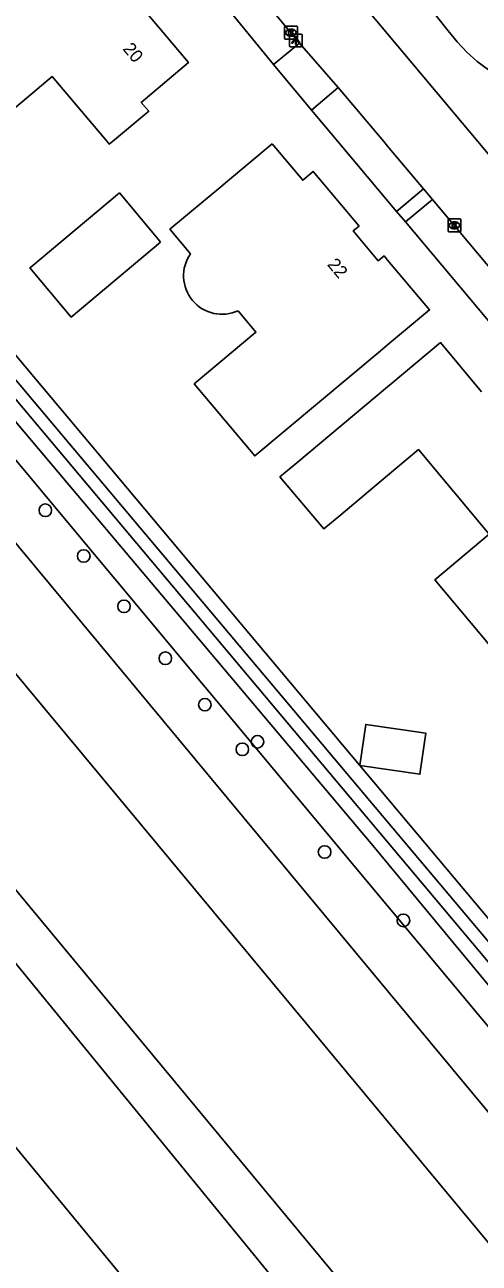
# Model space of a CAD drawing. Extents: x 157321 to 158827, y 386650 to 388532.
# Drawn here: x 157971.7 to 158007.1, y 386912.6 to 387009.1 of the extents above; entities that cross this region are included whole.
import ezdxf

# ---------------------------------------------------------------- set-up
doc = ezdxf.new("R2010")
doc.units = 0
for name, color, linetype in [('IMGEO_Boom', 7, 'Continuous'), ('IMGEO_Fietspad_gesloten', 7, 'Continuous'), ('IMGEO_Groenvoorziening', 7, 'Continuous'), ('IMGEO_Kolk', 7, 'Continuous'), ('IMGEO_Lichtpunt', 7, 'Continuous'), ('IMGEO_Loofbos', 7, 'Continuous'), ('IMGEO_Pand', 7, 'Continuous'), ('IMGEO_Pand_nummerreeks', 7, 'Continuous'), ('IMGEO_Rijbaan_lokaal_gesloten', 7, 'Continuous'), ('IMGEO_Voetpad_open', 7, 'Continuous'), ('IMGEO_Waterloop', 7, 'Continuous')]:
    doc.layers.add(name, color=color, linetype=linetype)

msp = doc.modelspace()

# ---------------------------------------------------------------- linework, layer by layer
at = {"layer": 'IMGEO_Boom'}
for centre in [(157973.337, 386971.279), (157976.332, 386967.714), (157979.465, 386963.801), (157982.691, 386959.755), (157985.765, 386956.139), (157989.865, 386953.249), (157988.683, 386952.66), (157995.089, 386944.665), (158001.231, 386939.336)]:
    msp.add_circle(centre, 0.489, dxfattribs=at)
at = {"layer": 'IMGEO_Fietspad_gesloten'}
msp.add_lwpolyline([(158000, 387014.593), (158004.726, 387008.62), (158005.406, 387007.76), (158006.16, 387006.964), (158006.983, 387006.238), (158007.867, 387005.589), (158008.805, 387005.021), (158009.791, 387004.54), (158010.815, 387004.148), (158011.87, 387003.85), (158012.948, 387003.647), (158014.039, 387003.541), (158015.136, 387003.533), (158016.229, 387003.623), (158017.31, 387003.81), (158018.369, 387004.093), (158019.399, 387004.47), (158020.111, 387004.794), (158022.082, 387005.73), (158023.75, 387006.523)], dxfattribs=at)
at = {"layer": 'IMGEO_Groenvoorziening'}
for points in [[(158032.15, 386861.115), (158029.801, 386864.464), (158027.255, 386867.666), (158023.027, 386872.512), (158000, 386900.579), (157928.219, 386988.333), (157917.785, 387000), (157871.791, 387051.43), (157870.977, 387052.41)], [(157915.669, 387039.524), (157916.246, 387034.499), (157917.326, 387029.652), (157918.224, 387026.707), (157925.534, 387014.398), (157933.739, 387003.394), (158036.298, 386879.994), (158040.875, 386875.274), (158045.999, 386870.991), (158051.541, 386867.268), (158057.356, 386864.191), (158059.718, 386863.157), (158065.313, 386860.377), (158069.288, 386859.404), (158071.922, 386859.047), (158074.577, 386858.967), (158077.228, 386859.164), (158080.09, 386859.682), (158109.645, 386869.131), (158107.666, 386875.322)], [(157937.472, 387021.971), (157943.823, 387013.736), (157955.389, 387000), (158000, 386947.022), (158042.278, 386896.814)], [(157991.12, 387006.005), (157981.864, 387017.312), (157978.709, 387020.934)], [(157938.087, 387014.677), (157950.334, 387000), (158000, 386940.482), (158039.093, 386893.634)], [(157939.879, 387006.192), (157945.025, 387000), (158000, 386933.844), (158041.131, 386884.348)], [(157951.635, 387006.472), (157997.832, 386951.408)], [(158000.702, 386994.555), (157996.119, 387000), (157994.061, 387002.445)], [(157923.674, 387000), (157926.719, 386995.12), (158000, 386906.805), (158021.479, 386880.919), (158025.173, 386876.788)], [(158018.379, 386973.505), (158001.394, 386993.731)], [(157997.832, 386951.408), (158016.34, 386929.351), (158048.856, 386891.347), (158052.006, 386888.362), (158054.735, 386886.23), (158061.143, 386882.788), (158063.836, 386881.61), (158066.74, 386880.636), (158072.605, 386879.295), (158075.571, 386878.874), (158081.422, 386878.627), (158087.103, 386878.964), (158090.042, 386879.509), (158092.91, 386880.238), (158101.35, 386883.538), (158104.009, 386884.795), (158111.36, 386888.673), (158097.876, 386904.822), (158091.265, 386912.857)]]:
    msp.add_lwpolyline(points, dxfattribs=at)
at = {"layer": 'IMGEO_Kolk'}
for p, q in [((157991.969, 387008.048), (157991.969, 387008.9)), ((157992.044, 387008.974), (157992.896, 387008.974)), ((157992.457, 387008.754), (157992.482, 387008.754)), ((157992.97, 387008.9), (157992.97, 387008.048)), ((157992.896, 387007.974), (157992.044, 387007.974)), ((157992.48, 387008.194), (157992.455, 387008.194)), ((158004.706, 386993.048), (158004.706, 386993.9)), ((158004.781, 386993.974), (158005.633, 386993.974)), ((158005.217, 386993.194), (158005.192, 386993.194)), ((158005.194, 386993.754), (158005.219, 386993.754)), ((158005.707, 386993.9), (158005.707, 386993.048)), ((158005.633, 386992.974), (158004.781, 386992.974))]:
    msp.add_line(p, q, dxfattribs=at)
for points in [[(157991.969, 387008.048), (157991.969, 387008.9)], [(157992.044, 387008.974), (157992.896, 387008.974)], [(157992.29, 387008.674), (157992.413, 387008.674), (157992.413, 387008.523), (157992.543, 387008.674), (157992.707, 387008.674), (157992.561, 387008.523), (157992.714, 387008.274), (157992.562, 387008.274), (157992.477, 387008.438), (157992.413, 387008.371), (157992.413, 387008.274), (157992.29, 387008.274), (157992.29, 387008.674)], [(157992.97, 387008.9), (157992.97, 387008.048)], [(157992.896, 387007.974), (157992.044, 387007.974)], [(158004.706, 386993.048), (158004.706, 386993.9)], [(158004.781, 386993.974), (158005.633, 386993.974)], [(158005.027, 386993.674), (158005.15, 386993.674), (158005.15, 386993.523), (158005.28, 386993.674), (158005.444, 386993.674), (158005.298, 386993.523), (158005.451, 386993.274), (158005.299, 386993.274), (158005.214, 386993.438), (158005.15, 386993.371), (158005.15, 386993.274), (158005.027, 386993.274), (158005.027, 386993.674)], [(158005.707, 386993.9), (158005.707, 386993.048)], [(158005.633, 386992.974), (158004.781, 386992.974)]]:
    msp.add_lwpolyline(points, dxfattribs=at)
for centre, start, end in [((157992.046, 387008.898), 91.55205, 178.44795), ((157992.046, 387008.898), 91.55205, 178.44795), ((157992.894, 387008.898), 1.55205, 88.44795), ((157992.894, 387008.898), 1.55205, 88.44795), ((157992.046, 387008.05), 181.55205, 268.44795), ((157992.046, 387008.05), 181.55205, 268.44795), ((157992.894, 387008.05), 271.55205, 358.44795), ((157992.894, 387008.05), 271.55205, 358.44795), ((158004.783, 386993.898), 91.55205, 178.44795), ((158004.783, 386993.898), 91.55205, 178.44795), ((158005.631, 386993.898), 1.55205, 88.44795), ((158005.631, 386993.898), 1.55205, 88.44795), ((158004.783, 386993.05), 181.55205, 268.44795), ((158004.783, 386993.05), 181.55205, 268.44795), ((158005.631, 386993.05), 271.55205, 358.44795), ((158005.631, 386993.05), 271.55205, 358.44795)]:
    msp.add_arc(centre, 0.0765, start, end, dxfattribs=at)
for centre, major_axis, ratio, start_param, end_param in [((157992.456, 387008.474), (-0.387, 0.002), 0.722429, 4.712389, 7.853982), ((157992.481, 387008.474), (-0.39, 0.002), 0.717154, 1.570796, 4.712389), ((158005.193, 386993.474), (-0.387, 0.002), 0.722429, 4.712389, 7.853982), ((158005.218, 386993.474), (-0.39, 0.002), 0.717154, 1.570796, 4.712389)]:
    msp.add_ellipse(centre, major_axis=major_axis, ratio=ratio, start_param=start_param, end_param=end_param, dxfattribs=at)
at = {"layer": 'IMGEO_Lichtpunt'}
for p, q in [((157992.35, 387008.271), (157992.35, 387007.464)), ((157992.35, 387008.271), (157992.35, 387007.464)), ((157993.252, 387008.366), (157992.444, 387008.366)), ((157993.252, 387008.366), (157992.444, 387008.366)), ((157993.346, 387007.464), (157993.346, 387008.271)), ((157993.346, 387007.464), (157993.346, 387008.271)), ((157992.444, 387007.37), (157993.252, 387007.37)), ((157992.444, 387007.37), (157993.252, 387007.37))]:
    msp.add_line(p, q, dxfattribs=at)
for points in [[(157992.724, 387007.935), (157992.763, 387007.907), (157992.575, 387007.645), (157992.537, 387007.672), (157992.724, 387007.935)], [(157992.826, 387007.887), (157992.873, 387007.887), (157992.873, 387007.565), (157992.826, 387007.565), (157992.826, 387007.887)], [(157992.936, 387007.907), (157992.974, 387007.934), (157993.161, 387007.672), (157993.122, 387007.644), (157992.936, 387007.907)]]:
    msp.add_lwpolyline(points, dxfattribs=at)
msp.add_circle((157992.849, 387008.069), 0.0994, dxfattribs=at)
for centre, start, end in [((157992.444, 387008.271), 90, 180), ((157992.444, 387008.271), 90, 180), ((157993.252, 387008.271), 0, 90), ((157993.252, 387008.271), 0, 90), ((157992.444, 387007.464), 180, 270), ((157992.444, 387007.464), 180, 270), ((157993.252, 387007.464), 270, 0), ((157993.252, 387007.464), 270, 360)]:
    msp.add_arc(centre, 0.0946, start, end, dxfattribs=at)
at = {"layer": 'IMGEO_Loofbos'}
msp.add_lwpolyline([(158038.982, 386833.681), (158041.689, 386835.911), (158004.244, 386881.346), (157903.574, 387003.498), (157866.09, 387048.992)], dxfattribs=at)
at = {"layer": 'IMGEO_Pand'}
for points in [[(157980.253, 387011.189), (157984.479, 387006.146), (157980.809, 387003.048), (157981.39, 387002.359), (157978.567, 387000), (157978.32, 386999.794), (157978.146, 387000), (157973.873, 387005.054), (157967.839, 387000), (157966.986, 386999.286), (157966.386, 387000), (157961.965, 387005.291), (157969.332, 387011.446), (157965.549, 387015.974), (157970.468, 387020.084), (157973.65, 387016.275), (157976.795, 387012.511), (157978.867, 387010.031), (157980.253, 387011.189)], [(157984.645, 386991.256), (157983.045, 386993.162), (157987.163, 386996.612), (157987.378, 386996.792), (157990.995, 386999.823)], [(157990.995, 386999.823), (157993.395, 386996.984), (157994.208, 386997.671), (157997.781, 386993.415), (157997.322, 386993.03), (157999.27, 386990.709), (157999.729, 386991.094), (158000, 386990.771), (158003.264, 386986.881), (158000, 386984.153), (157999.428, 386983.675), (157989.657, 386975.511), (157984.94, 386981.114), (157989.74, 386985.139), (157988.369, 386986.825)], [(157982.31, 386992.161), (157982.121, 386992.386), (157979.117, 386995.999), (157972.203, 386990.223), (157972.139, 386990.169), (157975.353, 386986.322), (157982.31, 386992.161)], [(158000, 386980.903), (158000.279, 386981.136), (158004.114, 386984.343), (158007.316, 386980.509)], [(158009.198, 386959.269), (158003.685, 386965.861), (158007.917, 386969.425), (158002.409, 386976), (158000, 386973.982), (157996.362, 386970.934), (157995.044, 386969.83), (157991.606, 386973.883), (157992.925, 386974.986), (158000, 386980.903)], [(157997.832, 386951.408), (157998.299, 386954.602), (158002.985, 386953.918), (158002.518, 386950.723), (157997.832, 386951.408)]]:
    msp.add_lwpolyline(points, dxfattribs=at)
msp.add_arc((157987.106, 386989.544), 2.998, 145.17411, 294.91612, dxfattribs=at)
at = {"layer": 'IMGEO_Rijbaan_lokaal_gesloten'}
for points in [[(157972.38, 387041.273), (158000, 387008.374), (158007.03, 387000), (158030.213, 386972.386), (158034.557, 386967.207)], [(157993.128, 387007.669), (157983.795, 387018.928), (157980.721, 387022.628)], [(157996.153, 387004.218), (157993.128, 387007.669)], [(158002.787, 386996.322), (158000, 386999.639), (157999.697, 387000), (157996.153, 387004.218)], [(158003.5, 386995.491), (158002.787, 386996.322)], [(158020.47, 386975.229), (158003.5, 386995.491)]]:
    msp.add_lwpolyline(points, dxfattribs=at)
at = {"layer": 'IMGEO_Voetpad_open'}
for points in [[(157991.12, 387006.005), (157993.128, 387007.669)], [(157994.061, 387002.445), (157991.12, 387006.005)], [(157994.061, 387002.445), (157996.153, 387004.218)], [(158002.787, 386996.322), (158000.702, 386994.555)], [(158003.5, 386995.491), (158001.394, 386993.731)], [(158001.394, 386993.731), (158000.702, 386994.555)]]:
    msp.add_lwpolyline(points, dxfattribs=at)
at = {"layer": 'IMGEO_Waterloop'}
for points in [[(158095.701, 386911.342), (158111.4, 386892.389), (158113.022, 386890.458), (158113.833, 386888.489), (158112.829, 386886.635), (158101.398, 386881.267), (158093.944, 386878.448), (158091.801, 386878.081), (158083.999, 386876.845), (158071.525, 386877.849), (158063.26, 386880.012), (158059.862, 386881.556), (158050.67, 386886.616), (158047.349, 386889.435), (158044.337, 386892.64), (157951.031, 387003.711), (157941.028, 387015.529), (157936.703, 387021.226), (157932.995, 387028.081), (157930.292, 387037.813), (157929.635, 387046.889), (157929.79, 387051.06), (157930.408, 387058.32), (157934.617, 387071.335)], [(157932.204, 387070.08), (157929.693, 387061.429), (157928.612, 387057.181), (157927.955, 387046.676), (157928.805, 387037.253), (157931.586, 387027.907), (157935.448, 387020.801), (157938.923, 387016.244), (157998.707, 386945.337), (158035.782, 386900.577), (158043.159, 386891.424), (158050.149, 386885.438), (158062.314, 386879.181), (158071.815, 386876.632), (158084.328, 386875.937), (158092.747, 386877.096), (158100.007, 386879.259), (158111.632, 386884.434), (158113.447, 386885.476), (158114.335, 386886.828), (158115.146, 386888.643), (158114.722, 386890.304), (158096.532, 386911.95), (158095.701, 386911.342)]]:
    msp.add_lwpolyline(points, dxfattribs=at)

# ---------------------------------------------------------------- texts
at = {"layer": 'IMGEO_Pand_nummerreeks'}
for s, rotation, p in [('20', 309.9636, (157979.324, 387007.192)), ('22', 310.0037, (157995.251, 386990.396))]:
    msp.add_text(s, height=1, rotation=rotation, dxfattribs=at).set_placement(p)

doc.saveas('drawing.dxf')
